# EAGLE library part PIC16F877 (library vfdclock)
PIC 8 bit micro controller.
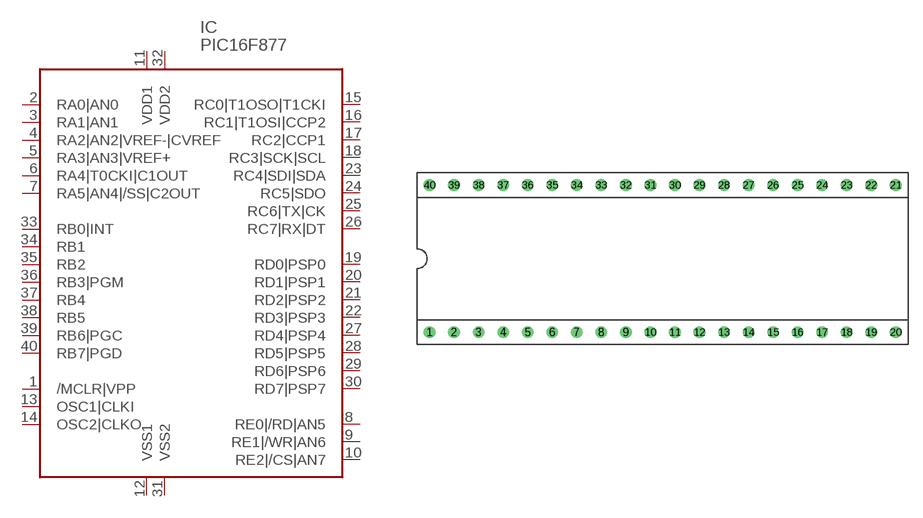
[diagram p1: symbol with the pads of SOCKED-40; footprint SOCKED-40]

Designator prefix IC

## PIC16F877A  [SOCKED-40]
1  /MCLR|VPP  in
2  RA0|AN0
3  RA1|AN1
4  RA2|AN2|VREF-|CVREF
5  RA3|AN3|VREF+
6  RA4|T0CKI|C1OUT
7  RA5|AN4|/SS|C2OUT
8  RE0|/RD|AN5
9  RE1|/WR|AN6
10  RE2|/CS|AN7
11  VDD1  pwr
12  VSS1  pwr
13  OSC1|CLKI  in
14  OSC2|CLKO  out
15  RC0|T1OSO|T1CKI
16  RC1|T1OSI|CCP2
17  RC2|CCP1
18  RC3|SCK|SCL
19  RD0|PSP0
20  RD1|PSP1
21  RD2|PSP2
22  RD3|PSP3
23  RC4|SDI|SDA
24  RC5|SDO
25  RC6|TX|CK
26  RC7|RX|DT
27  RD4|PSP4
28  RD5|PSP5
29  RD6|PSP6
30  RD7|PSP7
31  VSS2  pwr
32  VDD2  pwr
33  RB0|INT
34  RB1
35  RB2
36  RB3|PGM
37  RB4
38  RB5
39  RB6|PGC
40  RB7|PGD

## Footprint SOCKED-40 (pad centres in mm)
Dual In Line Socket
drill 0.7 round: 1 -24.13,-7.62; 2 -21.59,-7.62; 3 -19.05,-7.62; 4 -16.51,-7.62; 5 -13.97,-7.62; 6 -11.43,-7.62; 7 -8.89,-7.62; 8 -6.35,-7.62; 9 -3.81,-7.62; 10 -1.27,-7.62; 11 1.27,-7.62; 12 3.81,-7.62; 13 6.35,-7.62; 14 8.89,-7.62; 15 11.43,-7.62; 16 13.97,-7.62; 17 16.51,-7.62; 18 19.05,-7.62; 19 21.59,-7.62; 20 24.13,-7.62; 21 24.13,7.62; 22 21.59,7.62; 23 19.05,7.62; 24 16.51,7.62; 25 13.97,7.62; 26 11.43,7.62; 27 8.89,7.62; 28 6.35,7.62; 29 3.81,7.62; 30 1.27,7.62; 31 -1.27,7.62; 32 -3.81,7.62; 33 -6.35,7.62; 34 -8.89,7.62; 35 -11.43,7.62; 36 -13.97,7.62; 37 -16.51,7.62; 38 -19.05,7.62; 39 -21.59,7.62; 40 -24.13,7.62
